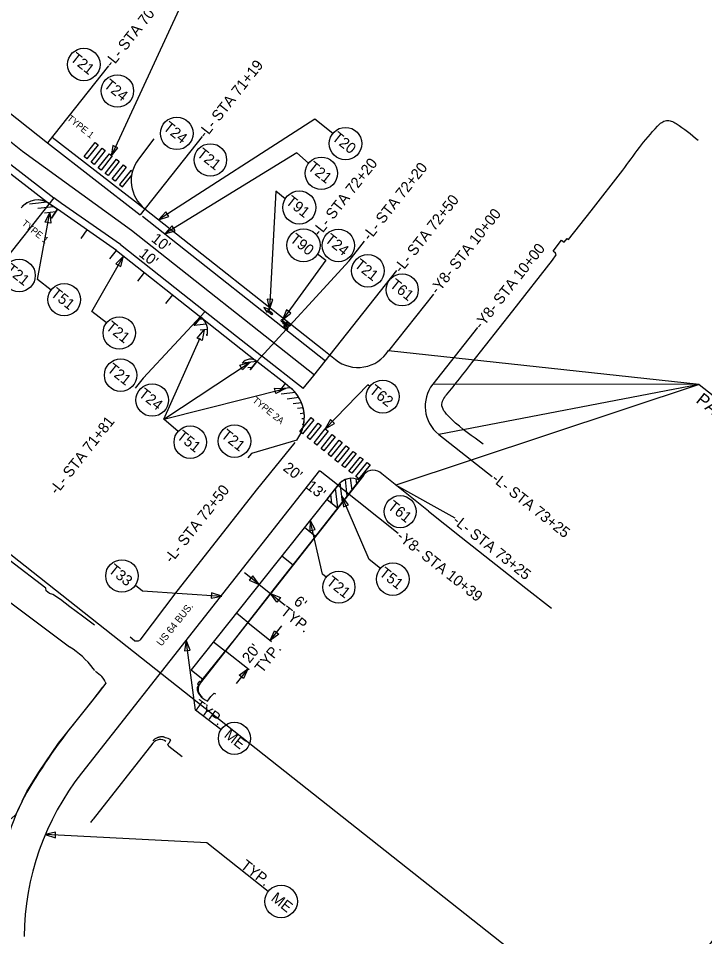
# Model space of a CAD drawing. Extents: x 553958 to 562499, y 493978 to 516388.
# Drawn here: x 558217 to 558599, y 506237 to 506749 of the extents above; entities that cross this region are included whole.
import ezdxf

# ---------------------------------------------------------------- set-up
doc = ezdxf.new("R2010")
doc.units = 0
for name, color, linetype in [('Prop Approach Slab', 7, 'Continuous'), ('Prop Conc 4in Sidewalk', 7, 'Continuous'), ('Prop EOT', 7, 'Continuous'), ('Prop Erosion Rip Rap Class II Label', 7, 'Continuous'), ('Prop Horizontal Alignment Tick Small', 7, 'Continuous'), ('Prop SS Fill Line', 7, 'Continuous'), ('Prop Superelevation Label', 7, 'Continuous'), ('Raster_Level_0', 7, 'Continuous'), ('Scratch_Level_0', 7, 'Continuous'), ('Scratch_Level_4', 7, 'Continuous'), ('Sheet North Arrow CELL', 7, 'Continuous'), ('Sheet Plan CELL', 7, 'Continuous'), ('Sheet Plot Border Inside CELL', 7, 'Continuous')]:
    doc.layers.add(name, color=color, linetype=linetype)

msp = doc.modelspace()

# ---------------------------------------------------------------- linework, layer by layer
at = {"layer": 'Prop Approach Slab'}
for p, q in [((558267.14, 506722.66), (558233.17, 506679.7)), ((558319.22, 506683.22), (558284.68, 506639.53)), ((558236.58, 506649.04), (558201.37, 506604.52)), ((558401.12, 506614.01), (558409.77, 506624.95)), ((558349.76, 506557.92), (558401.12, 506614.01)), ((558381.46, 506550.04), (558427.79, 506608.63)), ((558448.04, 506595.43), (558423.1, 506563.88)), ((558321.01, 506585.74), (558286.37, 506548.65)), ((558472.65, 506576.73), (558447.71, 506545.19)), ((558286.37, 506548.65), (558281.88, 506542.96)), ((558371.95, 506514.09), (558346.72, 506506.54)), ((558451.04, 506517.25), (558480.74, 506493.76)), ((558346.72, 506506.54), (558344.78, 506504.09)), ((558394.67, 506489.08), (558428.39, 506462.24)), ((558460.19, 506470.56), (558427.13, 506489.02))]:
    msp.add_line(p, q, dxfattribs=at)
for points in [[(558596.06, 506545.11), (558596.06, 506545.11), (558423.1, 506563.88)], [(558596.06, 506545.11), (558596.06, 506545.11), (558427.13, 506489.02)], [(558596.06, 506545.11), (558596.06, 506545.11), (558447.71, 506545.19)], [(558596.06, 506545.11), (558596.06, 506545.11), (558451.04, 506517.25)], [(558596.06, 506545.11), (558596.06, 506545.11), (558682.58, 506477.15)]]:
    msp.add_lwpolyline(points, dxfattribs=at)
at = {"layer": 'Prop EOT'}
for p, q in [((558235.65, 506682.88), (558287.33, 506642.92)), ((558199.3, 506677.87), (558236.58, 506649.04)), ((558233.17, 506679.7), (558284.68, 506639.53)), ((558202.77, 506670.03), (558234.28, 506645.76)), ((558321.01, 506585.74), (558352.24, 506561.06)), ((558318.53, 506582.6), (558349.76, 506557.92))]:
    msp.add_line(p, q, dxfattribs=at)
at = {"layer": 'Prop Erosion Rip Rap Class II Label'}
for points in [[(557425.46, 506933.59), (557889.73, 506539.36), (558124.72, 506519.69), (558557.87, 506177.2), (558959.56, 506684.21), (558454.57, 507154), (558185.43, 507366.81), (557535.46, 507286.55), (557335.3, 506986.11)], [(558124.72, 506519.69), (558557.87, 506177.2), (558410.26, 505507.28), (557974.76, 505851.63), (557743.04, 506034.85)]]:
    msp.add_lwpolyline(points, close=True, dxfattribs=at)
at = {"layer": 'Prop Horizontal Alignment Tick Small'}
for p, q in [((558363.37, 506580.11), (558363.46, 506580.23)), ((558363.37, 506580.11), (558363.46, 506580.23)), ((558363.96, 506580.88), (558364.06, 506581)), ((558363.96, 506580.88), (558364.06, 506581)), ((558364.18, 506580.14), (558364.3, 506580.45)), ((558364.43, 506578.82), (558364.18, 506580.14)), ((558364.3, 506580.45), (558365.68, 506579.5)), ((558365.33, 506579.37), (558364.43, 506579.99)), ((558364.43, 506579.99), (558364.68, 506578.63)), ((558364.68, 506578.63), (558364.43, 506578.82)), ((558365.07, 506578.39), (558365.33, 506579.37)), ((558365.83, 506578.03), (558365.07, 506578.39)), ((558365.55, 506579.27), (558365.35, 506578.52)), ((558365.35, 506578.52), (558365.93, 506578.24)), ((558365.59, 506576.54), (558365.44, 506576.35)), ((558365.59, 506576.54), (558365.44, 506576.35)), ((558366.63, 506577.6), (558365.55, 506579.27)), ((558365.68, 506579.5), (558366.83, 506577.73)), ((558365.93, 506578.24), (558365.83, 506578.03)), ((558366.24, 506577.38), (558366.09, 506577.18)), ((558366.24, 506577.38), (558366.09, 506577.18)), ((558366.83, 506577.73), (558366.65, 506577.58)), ((558367.09, 506578.47), (558366.94, 506578.28)), ((558367.09, 506578.47), (558366.94, 506578.28)), ((558367.74, 506579.31), (558367.59, 506579.12)), ((558367.74, 506579.31), (558367.59, 506579.12))]:
    msp.add_line(p, q, dxfattribs=at)
msp.add_lwpolyline([(558355.54, 506585.18), (558355.47, 506586.11), (558358.14, 506584.01), (558358.53, 506584.51), (558355.86, 506586.61), (558356.79, 506586.76), (558353.62, 506587.97)], close=True, dxfattribs=at)
msp.add_lwpolyline([(558355.54, 506585.18), (558355.47, 506586.11), (558358.14, 506584.01), (558358.53, 506584.51), (558355.86, 506586.61), (558356.79, 506586.76), (558353.62, 506587.97)], close=True, dxfattribs=at)
for radius, start, end in [(0.563, 52.2816, 232.2816), (0.563, 52.2816, 232.2816), (0.41, 232.2816, 52.2816)]:
    msp.add_arc((558363.71, 506580.55), radius, start, end, dxfattribs=at)
for centre, major_axis, ratio, start_param, end_param in [((558365.84, 506576.86), (1.18, -0.91), 0.435841, 1.570796, 4.712389), ((558365.84, 506576.86), (0.99, -0.765), 0.325967, 1.570796, 4.712389), ((558365.84, 506576.86), (1.18, -0.91), 0.435841, 4.712389, 7.853982), ((558365.84, 506576.86), (0.99, -0.765), 0.325967, 4.712389, 7.853982), ((558367.34, 506578.8), (1.18, -0.91), 0.435841, 1.570796, 4.712389), ((558367.34, 506578.8), (0.99, -0.765), 0.325967, 1.570796, 4.712389), ((558367.34, 506578.8), (1.18, -0.91), 0.435841, 4.712389, 7.853982), ((558367.34, 506578.8), (0.99, -0.765), 0.325967, 4.712389, 7.853982)]:
    msp.add_ellipse(centre, major_axis=major_axis, ratio=ratio, start_param=start_param, end_param=end_param, dxfattribs=at)
at = {"layer": 'Prop SS Fill Line'}
for p, q in [((558292.25, 506681.96), (558283.74, 506670.63)), ((558287.33, 506642.92), (558387.02, 506564.18)), ((558387.02, 506564.18), (558393.52, 506558.94)), ((558409.18, 506494.37), (558318.16, 506378.58)), ((558257.93, 506368.61), (558263.82, 506376.3)), ((558243.08, 506349.97), (558257.93, 506368.61)), ((558239.29, 506345.09), (558243.08, 506349.97)), ((558228.33, 506328.9), (558239.29, 506345.09)), ((558291.84, 506345.1), (558258.61, 506302.82)), ((558221.55, 506318.15), (558228.33, 506328.9)), ((558218.91, 506312.79), (558221.55, 506318.15))]:
    msp.add_line(p, q, dxfattribs=at)
for centre, radius, start, end in [((558299.72, 506658.61), 20, 143.0617, 231.6978), ((558406.06, 506574.52), 20, 231.1706, 327.9836), ((558463.49, 506532.9), 20, 142.1119, 231.5181), ((558322.16, 506375.23), 5.21, 139.9852, 236.8998), ((558295.91, 506342.11), 5.05, 51.4269, 143.6791), ((558334.66, 506255.85), 129, 153.8089, 181.2908), ((558352.95, 506228.67), 120, 141.8306, 142.9933)]:
    msp.add_arc(centre, radius, start, end, dxfattribs=at)
at = {"layer": 'Raster_Level_0'}
for p, q in [((557928.68, 506904.52), (558219.1, 506675.14)), ((558219.1, 506675.14), (558279.82, 506631.01)), ((558279.82, 506631.01), (558381.79, 506550.47)), ((558384.58, 506497.06), (558252.08, 506328.5))]:
    msp.add_line(p, q, dxfattribs=at)
msp.add_arc((558370.01, 506235.8), 150, 141.8306, 179.4263, dxfattribs=at)
at = {"layer": 'Scratch_Level_0'}
for p, q in [((558445.37, 506474.37), (558419.36, 506495.27)), ((558221.51, 506416.52), (558202.8, 506430.39)), ((558245.43, 506398.72), (558221.51, 506416.52)), ((558281.52, 506402.26), (558279.21, 506404.17)), ((558281.52, 506402.26), (558279.21, 506404.17)), ((558259.5, 506385.72), (558258.5, 506386.74)), ((558259.76, 506385.34), (558262.54, 506383.09))]:
    msp.add_line(p, q, dxfattribs=at)
for points in [[(558469.55, 506557.18), (558492.33, 506586.12), (558514.45, 506614.4), (558516.54, 506617.22), (558516.03, 506618.2), (558514.8, 506619.28), (558519.41, 506625.4), (558520.98, 506624.42), (558522.52, 506626.4), (558523.4, 506625.92), (558535.97, 506641.81), (558553.65, 506664.42)], [(558370.84, 506512.75), (558349.42, 506486.21), (558327.04, 506457.64), (558305.21, 506429.92), (558284.53, 506402.58)], [(558370.84, 506512.75), (558349.42, 506486.21), (558327.04, 506457.64), (558305.21, 506429.92), (558284.53, 506402.58)], [(558409.55, 506495.04), (558405.08, 506489.43), (558402.64, 506486.35)], [(558402.48, 506486.14), (558398.64, 506481.32), (558396.99, 506479.22), (558381.74, 506459.58), (558359.41, 506431.29), (558337.74, 506403.64), (558319.13, 506380.46), (558318.27, 506379.22), (558317.68, 506379.66), (558316.61, 506378.14), (558317.36, 506377.56), (558316.98, 506377.08)], [(558259.33, 506410.84), (558252.55, 506415.91), (558245.48, 506421.08), (558240.32, 506425.14), (558236.14, 506427.97), (558234.14, 506428.47), (558232.29, 506430), (558232.12, 506431.57), (558212.27, 506446.74), (558203.26, 506453.38), (558193, 506461.97), (558193.44, 506462.7), (558194.35, 506462.73), (558196.07, 506463.73), (558195.67, 506464.37), (558197.03, 506465.92), (558206.28, 506477.79)], [(558445.37, 506474.37), (558463.6, 506459.99), (558499.5, 506431.58), (558513.9, 506420.39)], [(558265.29, 506379.24), (558265.58, 506378.54), (558261.26, 506372.99), (558248.8, 506357.33)], [(558318.27, 506379.22), (558317.68, 506379.66), (558316.61, 506378.14), (558317.36, 506377.56), (558316.98, 506377.08)], [(558322.29, 506368.45), (558324.15, 506371.09), (558325.98, 506372.95), (558326.72, 506372.58)], [(558322.29, 506368.45), (558324.15, 506371.09), (558325.98, 506372.95), (558326.72, 506372.58)], [(558308.15, 506337.54), (558300.6, 506343.3), (558300.08, 506344.59), (558300.94, 506345.41), (558301.8, 506347.06), (558301.02, 506347.39)], [(558220.05, 506315.07), (558217.3, 506309.46), (558215.39, 506305.29), (558212.88, 506303.02), (558211.62, 506304.46), (558206.76, 506299.35), (558203.8, 506295.34), (558201.04, 506294.56), (558198.63, 506293.71), (558197.82, 506292.42), (558197.48, 506291.59), (558195.91, 506291.34)]]:
    msp.add_lwpolyline(points, dxfattribs=at)
for centre, major_axis, ratio, start_param, end_param in [((558414.57, 506490.49), (-5.55, 3.89), 0.99784, 4.538123, 6.157994), ((558282.72, 506405.59), (3.33, 1.29), 0.984082, 4.005477, 4.880373), ((558282.72, 506405.59), (3.33, 1.29), 0.984082, 4.005477, 4.880373), ((558220.77, 506358.99), (46.38, 6.91), 0.99552, 0.487973, 0.869621), ((558253.85, 506373.97), (6.05, 11.06), 0.999149, 5.643916, 6.022268), ((558499.25, 506158.11), (-260.6, -190.01), 0.991714, 4.97909, 5.137913)]:
    msp.add_ellipse(centre, major_axis=major_axis, ratio=ratio, start_param=start_param, end_param=end_param, dxfattribs=at)
for points in [[(558553.65, 506664.42), (558572.88, 506688.96), (558575.32, 506691.13), (558577.85, 506692.14), (558580.61, 506691.9), (558583.32, 506690.52), (558595.6, 506681.17)], [(558475.82, 506511.79), (558458.44, 506525.4), (558454.56, 506529.57), (558452.85, 506533.18), (558453.44, 506536.48), (558455.46, 506539.37), (558469.55, 506557.18)], [(558316.98, 506377.08), (558316.62, 506376.61), (558316.65, 506374.36), (558317.71, 506372.09), (558322.29, 506368.45)], [(558316.98, 506377.08), (558316.62, 506376.61), (558316.65, 506374.36), (558317.71, 506372.09), (558322.29, 506368.45)], [(558301.02, 506347.39), (558298.14, 506348.46), (558297.95, 506348.53), (558297.75, 506348.58), (558297.34, 506348.65), (558296.5, 506348.66), (558295.65, 506348.54), (558295.24, 506348.44), (558295.03, 506348.38), (558294.83, 506348.32), (558294.46, 506348.2), (558294.09, 506348.07), (558293.38, 506347.75), (558292.73, 506347.35), (558292.43, 506347.1), (558292.3, 506346.97), (558292.17, 506346.83), (558291.87, 506346.47)]]:
    msp.add_spline(points, degree=3, dxfattribs=at)
at = {"layer": 'Scratch_Level_4'}
for points in [[(558261.28, 506678.63), (558255.07, 506670.8), (558253.5, 506672.04), (558259.71, 506679.87)], [(558265.2, 506675.52), (558258.99, 506667.69), (558257.42, 506668.93), (558263.63, 506676.77)], [(558269.12, 506672.42), (558262.9, 506664.58), (558261.34, 506665.82), (558267.55, 506673.66)], [(558273.03, 506669.31), (558266.82, 506661.47), (558265.25, 506662.72), (558271.47, 506670.55)], [(558276.95, 506666.2), (558270.74, 506658.37), (558269.17, 506659.61), (558275.38, 506667.44)], [(558373.63, 506518.76), (558379.89, 506526.56), (558381.45, 506525.31), (558375.19, 506517.51)], [(558377.66, 506515.6), (558383.92, 506523.4), (558385.48, 506522.15), (558379.22, 506514.35)], [(558381.56, 506512.47), (558387.82, 506520.27), (558389.38, 506519.02), (558383.12, 506511.22)], [(558385.46, 506509.34), (558391.72, 506517.14), (558393.28, 506515.89), (558387.02, 506508.09)], [(558389.36, 506506.21), (558395.62, 506514.01), (558397.17, 506512.76), (558390.92, 506504.96)], [(558393.25, 506503.08), (558399.51, 506510.88), (558401.07, 506509.63), (558394.81, 506501.83)], [(558397.15, 506499.95), (558403.41, 506507.75), (558404.97, 506506.5), (558398.71, 506498.7)], [(558401.05, 506496.82), (558407.31, 506504.62), (558408.87, 506503.37), (558402.61, 506495.57)], [(558404.95, 506493.69), (558411.21, 506501.49), (558412.77, 506500.24), (558406.51, 506492.44)]]:
    msp.add_lwpolyline(points, close=True, dxfattribs=at)
msp.add_lwpolyline([(558280.35, 506663.58), (558279.43, 506664.31), (558273.22, 506656.47), (558274.78, 506655.23), (558279.98, 506661.78)], dxfattribs=at)
msp.add_arc((558299.72, 506658.61), 20, 165.6285, 170.8986, dxfattribs=at)
at = {"layer": 'Sheet North Arrow CELL'}
for p, q in [((558375.46, 506542.73), (558381.46, 506550.04)), ((558394.67, 506489.08), (558384.97, 506496.75))]:
    msp.add_line(p, q, dxfattribs=at)
at = {"layer": 'Sheet Plan CELL'}
for p, q in [((558297.84, 506525.75), (558346, 506557.41)), ((558297.84, 506525.75), (558365.6, 506542.87)), ((558351.02, 506433.63), (558342.81, 506440.11)), ((558357.3, 506428.61), (558365.5, 506422.12)), ((558357.87, 506401.65), (558344.61, 506412.14)), ((558357.09, 506402.27), (558363.58, 506410.47)), ((558345.46, 506385.96), (558332.21, 506396.45)), ((558344.64, 506386.61), (558338.15, 506378.41))]:
    msp.add_line(p, q, dxfattribs=at)
for points in [[(558323.44, 506814.59), (558331.33, 506808.33), (558268.46, 506672.25)], [(558392.01, 506684.91), (558382.08, 506692.91), (558294.99, 506636.86)], [(558378.52, 506668.36), (558371.92, 506674.14), (558298.44, 506629.05)], [(558365.49, 506648.45), (558360.38, 506652.75), (558356.72, 506586.79)], [(558235.09, 506597.68), (558227.59, 506603.61), (558234.37, 506640.85)], [(558265.96, 506579.35), (558257.84, 506585.78), (558275.45, 506616.62)], [(558383.56, 506617.81), (558388.16, 506614.35), (558364.06, 506581)], [(558305.84, 506518.92), (558297.84, 506525.75), (558318.14, 506571.12)], [(558412.65, 506544.01), (558411.62, 506544.83), (558387.82, 506520.27)], [(558418.55, 506442.47), (558412.21, 506447.59), (558397.12, 506482.73)], [(558388.39, 506437.62), (558386.27, 506439.29), (558379.46, 506469.48)], [(558282.02, 506433.16), (558285.99, 506430.02), (558330.2, 506427.07)], [(558329.72, 506352.69), (558315.48, 506363.5), (558310.27, 506402.52)], [(558356.1, 506262.54), (558321.89, 506289.59), (558231.76, 506294.23)]]:
    msp.add_lwpolyline(points, dxfattribs=at)
for points in [[(558269.48, 506678.16), (558268.46, 506672.25), (558272.3, 506676.86)], [(558231.8, 506635.43), (558234.37, 506640.85), (558234.86, 506634.87)], [(558299.03, 506641.31), (558294.99, 506636.86), (558300.71, 506638.69)], [(558302.56, 506633.4), (558298.44, 506629.05), (558304.19, 506630.76)], [(558273.92, 506610.82), (558275.45, 506616.62), (558271.22, 506612.36)], [(558355.49, 506592.66), (558356.72, 506586.79), (558358.59, 506592.49)], [(558366.19, 506586.61), (558364.04, 506581.01), (558368.71, 506584.78)], [(558316.44, 506570.86), (558320.3, 506575.46), (558319.26, 506569.55)], [(558340.22, 506555.82), (558346, 506557.41), (558341.79, 506553.14)], [(558359.6, 506542.96), (558365.6, 506542.87), (558360.36, 506539.95)], [(558390.73, 506525.51), (558387.82, 506520.27), (558392.96, 506523.35)], [(558400.84, 506478.01), (558397.12, 506482.73), (558397.98, 506476.79)], [(558382.25, 506464.17), (558379.46, 506469.48), (558379.22, 506463.48)], [(558345.51, 506436), (558351.02, 506433.63), (558347.43, 506438.44)], [(558324.32, 506425.91), (558330.2, 506427.07), (558324.52, 506429.01)], [(558360.88, 506423.79), (558357.3, 506428.61), (558362.81, 506426.23)], [(558361.9, 506405.85), (558357.09, 506402.27), (558359.47, 506407.77)], [(558312.52, 506396.96), (558310.27, 506402.52), (558309.44, 506396.58)], [(558339.82, 506383.03), (558344.64, 506386.61), (558342.26, 506381.11)], [(558237.62, 506295.48), (558231.76, 506294.23), (558237.46, 506292.38)]]:
    msp.add_lwpolyline(points, close=True, dxfattribs=at)
for centre, radius in [((558253.32, 506723.4), 9.06), ((558272, 506708.63), 9.06), ((558305.09, 506685.01), 9.06), ((558399.11, 506679.28), 9.06), ((558323.83, 506670.19), 9.06), ((558385.64, 506662.76), 9.06), ((558373.37, 506643.67), 9.22), ((558375.69, 506622.62), 9.22), ((558395.11, 506622.53), 9.06), ((558411.58, 506608.42), 9.06), ((558217.24, 506605.78), 9.06), ((558430.71, 506597.76), 8.94), ((558242.4, 506592.33), 9.06), ((558273.08, 506573.75), 9.06), ((558273.82, 506550.25), 9.06), ((558291.42, 506536.38), 9.06), ((558419.86, 506538.31), 9.19), ((558312.62, 506512.9), 9.06), ((558337.27, 506513.47), 9.06), ((558429.58, 506474.17), 8.94), ((558274.57, 506438.31), 9.06), ((558425.43, 506436.57), 9.06), ((558395.42, 506432.09), 8.94), ((558337.22, 506347.82), 8.94), ((558363.21, 506256.92), 9.06)]:
    msp.add_circle(centre, radius, dxfattribs=at)
at = {"layer": 'Sheet Plot Border Inside CELL'}
for p, q in [((558073.12, 506805.73), (558233.17, 506679.7)), ((558232.68, 506646.71), (558228.06, 506646.17)), ((558240.95, 506645.98), (558236.58, 506649.04)), ((558220.81, 506645.32), (558220.13, 506645.24)), ((558228.09, 506646.17), (558223.04, 506645.58)), ((558236.6, 506644.14), (558227.65, 506643.1)), ((558234.28, 506645.76), (558238.66, 506642.71)), ((558238.66, 506642.71), (558234.28, 506645.76)), ((558238.66, 506642.71), (558235.23, 506637.8)), ((558235.23, 506637.8), (558238.66, 506642.71)), ((558271.44, 506619.79), (558238.66, 506642.71)), ((558273.83, 506623), (558240.95, 506645.98)), ((558237.64, 506641.24), (558231.35, 506640.51)), ((558235.34, 506637.95), (558235.05, 506637.92)), ((558286.02, 506638.86), (558388, 506558.31)), ((558255.05, 506631.25), (558251.62, 506626.34)), ((558273.83, 506623), (558321.01, 506585.74)), ((558267.72, 506615.08), (558271.44, 506619.79)), ((558271.44, 506619.79), (558318.53, 506582.6)), ((558283.41, 506602.68), (558287.13, 506607.38)), ((558299.1, 506590.27), (558302.82, 506594.98)), ((558314.79, 506577.87), (558318.53, 506582.6)), ((558318.53, 506582.6), (558314.8, 506577.89)), ((558319.7, 506581.51), (558317.46, 506581.25)), ((558321.51, 506578.7), (558314.83, 506577.92)), ((558322.26, 506575.77), (558318.11, 506575.28)), ((558322.1, 506572.73), (558321.44, 506572.65)), ((558375.46, 506542.73), (558352.24, 506561.06)), ((558349.76, 506557.91), (558341.55, 506556.95)), ((558347.13, 506554.59), (558344.68, 506554.3)), ((558349.76, 506557.92), (558346.05, 506553.22)), ((558346.05, 506553.22), (558349.76, 506557.92)), ((558365.46, 506545.53), (558349.76, 506557.92)), ((558365.46, 506545.53), (558361.74, 506540.82)), ((558365.46, 506545.53), (558361.74, 506540.82)), ((558368.16, 506543.4), (558365.46, 506545.53)), ((558368.4, 506543.2), (558363.14, 506542.58)), ((558371.16, 506540.5), (558363.31, 506539.58)), ((558373.16, 506537.72), (558366.64, 506536.95)), ((558374.6, 506534.86), (558369.93, 506534.32)), ((558375.56, 506531.96), (558372.34, 506531.58)), ((558376.08, 506529), (558373.87, 506528.74)), ((558376.18, 506525.99), (558374.72, 506525.82)), ((558374.64, 506520.02), (558375.36, 506520.91)), ((558375.84, 506522.93), (558374.96, 506522.82)), ((558394.88, 506488.92), (558388.71, 506481.13)), ((558394.8, 506488.81), (558388.71, 506481.13)), ((558394.88, 506488.92), (558394.8, 506488.81)), ((558397.48, 506479.49), (558396.21, 506490.34)), ((558400.11, 506482.83), (558399.03, 506492.06)), ((558402.74, 506486.18), (558401.97, 506492.74)), ((558405.37, 506489.52), (558405.02, 506492.47)), ((558391.51, 506478.89), (558390.92, 506483.92)), ((558394.84, 506476.23), (558393.55, 506487.24)), ((558388.71, 506481.13), (558388.73, 506481.11)), ((558388.71, 506481.13), (558388.73, 506481.11)), ((558388.73, 506481.11), (558394.89, 506476.19)), ((558376.18, 506465.5), (558382.33, 506460.58)), ((558363.64, 506449.53), (558369.96, 506444.48)), ((558351.02, 506433.63), (558357.3, 506428.61)), ((558338.4, 506417.73), (558344.78, 506412.63)), ((558325.63, 506401.63), (558332.21, 506396.45))]:
    msp.add_line(p, q, dxfattribs=at)
for points in [[(558394.8, 506488.81), (558313.17, 506385.93), (558319.83, 506380.7)], [(558388.73, 506481.11), (558394.73, 506476.31), (558394.89, 506476.19)]]:
    msp.add_lwpolyline(points, dxfattribs=at)
for centre, radius, start, end in [((558227.56, 506636.14), 11.74, 55.0396, 141.6978), ((558227.56, 506636.14), 11.74, 115.4869, 136.5452), ((558227.56, 506636.14), 11.74, 55.0396, 88.1274), ((558312.35, 506574.78), 9.96, 345.1369, 51.6978), ((558312.35, 506574.78), 9.96, 345.1369, 51.6978), ((558346.14, 506553.34), 5.85, 51.6978, 143.2042), ((558346.14, 506553.34), 5.85, 51.6978, 143.2042), ((558355.05, 506526.8), 21.14, 323.0309, 51.6978), ((558355.05, 506526.8), 21.14, 343.8202, 51.6978), ((558402.66, 506482.97), 9.79, 63.1427, 143.4018), ((558402.66, 506482.97), 9.79, 63.1593, 142.5994)]:
    msp.add_arc(centre, radius, start, end, dxfattribs=at)

# ---------------------------------------------------------------- texts
at = {"layer": 'Prop Approach Slab'}
msp.add_text('PAVEMENT MARKINGS', height=7, rotation=321.6667, dxfattribs=at).set_placement((558593.89, 506535.42))
at = {"layer": 'Prop Conc 4in Sidewalk'}
for s, p in [('TYPE 1', (558243.62, 506692.76)), ('TYPE 1', (558218.36, 506634.22)), ('TYPE 2A', (558346.97, 506535.59))]:
    msp.add_text(s, height=3.75, rotation=321.3322, dxfattribs=at).set_placement(p)
at = {"layer": 'Prop Superelevation Label'}
msp.add_text('US 64 BUS.', height=4, rotation=51.6667, dxfattribs=at).set_placement((558296.61, 506398.86))
at = {"layer": 'Sheet Plan CELL'}
for s, rotation, p in [('-L- STA 70+54', 51.6698, (558269.09, 506721.26)), ('T21', 321.6667, (558245.34, 506725.89)), ('-L- STA 71+19', 51.6698, (558321.18, 506681.82)), ('T24', 321.6667, (558264.02, 506711.12)), ('T24', 321.6667, (558297.12, 506687.49)), ('T20', 321.6667, (558391.14, 506681.76)), ('T21', 321.6667, (558315.85, 506672.67)), ('T21', 321.6667, (558377.66, 506665.24)), ('-L- STA 72+20', 51.6698, (558384.77, 506627.13)), ('-L- STA 72+20', 51.6698, (558412.63, 506624.73)), ('T91', 321.6667, (558365.37, 506646.18)), ('-L- STA 72+50', 51.6698, (558430.15, 506606.77)), ('-Y8- STA 10+00', 51.6698, (558450.33, 506594.8)), ("10'", 321.6667, (558290.44, 506625.24)), ('T90', 321.6667, (558367.69, 506625.12)), ('T24', 321.6667, (558387.13, 506625.01)), ('-Y8- STA 10+00', 51.6698, (558474.84, 506575.42)), ("10'", 321.6667, (558283.56, 506616.97)), ('T21', 321.6667, (558209.27, 506608.26)), ('T21', 321.6667, (558403.61, 506610.91)), ('T61', 321.6667, (558423.3, 506599.8)), ('T51', 321.6667, (558234.42, 506594.81)), ('T21', 321.6667, (558265.11, 506576.23)), ('T21', 321.6667, (558265.84, 506552.73)), ('T62', 321.6667, (558411.88, 506540.79)), ('T24', 321.6667, (558283.44, 506538.86)), ('-L- STA 71+81', 51.6698, (558238.33, 506483.26)), ('T51', 321.6667, (558304.64, 506515.38)), ('T21', 321.6667, (558329.29, 506515.95)), ("20'", 321.6667, (558363.85, 506497.63)), ('-L- STA 73+25', 321.6667, (558480.07, 506491.62)), ('-L- STA 72+50', 51.6698, (558302.27, 506445.05)), ("13'", 321.6667, (558376.81, 506487.38)), ('T61', 321.6667, (558422.16, 506476.21)), ('-L- STA 73+25', 321.6667, (558458.33, 506468.21)), ('-Y8- STA 10+39', 321.6698, (558427.17, 506459.39)), ('T33', 321.6667, (558266.59, 506440.8)), ('T51', 321.6667, (558417.46, 506439.05)), ('T21', 321.6667, (558388.01, 506434.13)), (" 6'", 321.6684, (558368.05, 506424.5)), ('TYP.', 321.6684, (558362.47, 506417.44)), ("20'", 51.637, (558345.63, 506389.32)), ('TYP.', 51.637, (558352.69, 506383.74)), ('TYP.', 324.1314, (558313.99, 506365.08)), ('ME', 321.6667, (558331.02, 506348.83)), ('TYP.', 322.1481, (558340.2, 506275.95)), ('ME', 321.6667, (558357.19, 506257.86))]:
    msp.add_text(s, height=6, rotation=rotation, dxfattribs=at).set_placement(p)

doc.saveas('drawing.dxf')
